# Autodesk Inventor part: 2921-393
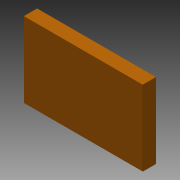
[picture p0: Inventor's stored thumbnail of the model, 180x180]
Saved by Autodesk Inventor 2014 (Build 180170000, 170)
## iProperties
Company: NHTSA/VRTC
Created: 2012-02
Part Number: 2921-393
Project: CHILD SIDE IMPACT SLED
Material: Generic
Description: SEAT BACK CUSHION COVER
Document SubType Name: Modeling
Designer: Mike Vanvoorhis
Density: 1 g/cm^3
Mass: 729.185 g
Surface Area: 17860.3 cm^2
Volume: 729.185 cm^3
Appearance: Orange
Title: Seat Back Cushion Cover
Subject: Child SIde Impact Sled
Author: Dave Walker
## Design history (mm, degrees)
sketch "Sketch1"
  geometry: L1 (-334, 211.5)-(334, 211.5); L2 (334, 211.5)-(334, -211.5); L3 (334, -211.5)-(-334, -211.5); L4 (-334, -211.5)-(-334, 211.5); L5 (0, 296.1)-(0, -296.1) reference; L6 (-467.6, 0)-(467.6, 0) reference
  constraints: 8 end point, 2 parallel, 1 horizontal, 1 perpendicular, 2 other
  dimensions: "d0" = 668 distance of L1.start L1.end; "d1" = 423 distance of L3.end L1.start
extrude "Extrusion1" new body sketch "Sketch1" distance "d2" = 0.81661; taper "d3" = 0 deg
sketch "Sketch2"
  geometry: L1 (0, 0)-(0, 0.817) reference; L2 (0, 0)-(668, 0); L3 (668, 0)-(668, 75); L4 (668, 75)-(0, 75); L5 (0, 75)-(0, 0); L6 (668, 0)-(668, 0.817) reference; 1 further point
  constraints: 8 end point, 2 parallel, 1 collinear, 1 horizontal, 1 perpendicular
  dimensions: "d4" = 75 distance of L2.end L3.end
extrude "Extrusion2" join sketch "Sketch2" distance "d5" = 0.81661; taper "d6" = 0 deg
mirror "Mirror1"
workplane "Work Plane1"
mirror "Mirror2"
sketch "Sketch3"
  geometry: L1 (75, 0)-(0, 0) reference; L2 (75, -424.633)-(0, -424.633) reference; L3 (75, -424.633)-(0, -424.633); L4 (0, -424.633)-(0, 0); L5 (0, 0)-(75, 0); L6 (75, 0)-(75, -424.633); 1 further point
  constraints: 8 end point, 2 parallel, 1 horizontal, 1 perpendicular
extrude "Extrusion3" join sketch "Sketch3" distance "d7" = 0.81661; taper "d8" = 0 deg
mirror "Mirror3"
sketch "Sketch4"
  geometry: L1 (0, 0)-(669.633, 0) reference; L2 (0, 424.633)-(0, 0) reference; 7 further points
  constraints: 4 horizontal alignment, 3 vertical alignment
  dimensions: "d9" = 55 distance from line of point (55, 55) L1; "d12" = 55 distance from line of point (55, 55) L2; "d22" = 335 distance from line of point (335, 55) L2; "d23" = 615 distance from line of point (615, 55) L2; "d24" = 370 distance from line of point (55, 370) L1
hole "Hole1" sketch "Sketch4" at (55, 55), (55, 370), (615, 55), (615, 370), (335, 370), (335, 55) diameter "d14" = 9.525; stored, may be unused: countersink angle "d18" = 90 deg, drill point angle "d20" = 118 deg; dims "d15" = 6, "d16" = 4, "d17" = 2, "d19" = 8
fillet "Fillet1" dims "d25" = 2
fillet "Fillet2" dims "d26" = 2
fillet "Fillet3" dims "d27" = 1
fillet "Fillet4" dims "d28" = 1
body "Solid1"
